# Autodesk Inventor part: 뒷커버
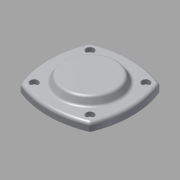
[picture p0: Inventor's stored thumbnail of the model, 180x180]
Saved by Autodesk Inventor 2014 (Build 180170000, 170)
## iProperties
Created: 2013-02
Part Number: 뒷커버
Document SubType Name: Modeling
Designer: 한국산업디자인학원[gmhk.co.kr]
Density: 2.71 g/cm^3
Material: 알루미늄 6061
Appearance: 알루미늄 - 평지
Mass: 225.473 g
Surface Area: 194.999 cm^2
Volume: 83.2003 cm^3
Author: 한국산업디자인학원[gmhk.co.kr]
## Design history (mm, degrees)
sketch "스케치1"
  geometry: C1 r 30 at (0, 0) reference; A1 r 91.05 centre (0, -48.55) between (34.185, 35.839) and (-34.185, 35.839) reference; A2 r 91.05 centre (48.55, 0) between (-35.839, 34.185) and (-35.839, -34.185) reference; A3 r 3 centre (-33.058, 33.058) between (-34.185, 35.839) and (-35.839, 34.185) reference; A4 r 3 centre (33.058, 33.058) between (35.839, 34.185) and (34.185, 35.839) reference; A5 r 91.05 centre (-48.55, 0) between (35.839, -34.185) and (35.839, 34.185) reference; A6 r 3 centre (33.058, -33.058) between (34.185, -35.839) and (35.839, -34.185) reference; A7 r 91.05 centre (0, 48.55) between (-34.185, -35.839) and (34.185, -35.839) reference; A8 r 3 centre (-33.058, -33.058) between (-35.839, -34.185) and (-34.185, -35.839) reference; 1 further point
  node "참조1"
  node "참조2"
  node "참조3"
  node "참조4"
  node "참조5"
  node "참조6"
  node "참조7"
  node "참조8"
  node "참조9"
extrude "돌출1" new body sketch "스케치1" distance "d0" = 8; taper "d1" = 0 deg
sketch "스케치2"
  geometry: C1 r 30 at (0, 0); 1 further point
  constraints: 1 centre point, 1 coincident
  dimensions: "d2" = 60 diameter of C1
extrude "돌출2" join sketch "스케치2" distance "d3" = 7; taper "d4" = -30 deg
sketch "스케치3"
  geometry: C1 r 1.621 at (28.284, 28.284) reference; C2 r 1.621 at (-28.284, 28.284) reference; C3 r 1.621 at (-28.284, -28.284) reference; C4 r 1.621 at (28.284, -28.284) reference; 1 further point
hole "구멍2" sketch "스케치3" at (28.284, 28.284), (28.284, -28.284), (-28.284, -28.284), (-28.284, 28.284) diameter "d14" = 4.5; stored, may be unused: countersink angle "d18" = 90 deg, drill point angle "d20" = 118 deg; dims "d15" = 6, "d16" = 8, "d17" = 4.4, "d19" = 20
extrude "돌출3" join sketch "스케치1" distance "d21" = 12; taper "d22" = 0 deg
hole "구멍3" diameter "d25" = 30; stored, may be unused: countersink angle "d29" = 90 deg, drill point angle "d31" = 0 deg; dims "d23" = 10, "d24" = 10, "d26" = 6, "d27" = 40, "d28" = 12, "d30" = 15
fillet "모깎기1" dims "d32" = 3, "d33" = 0.3
chamfer "모따기1" distance "d34" = 1; stored, may be unused: second distance "d35" = 2, angle "d36" = 45 deg
node "솔리드1"
node "참조10"
node "참조11"
node "참조12"
node "참조13"
